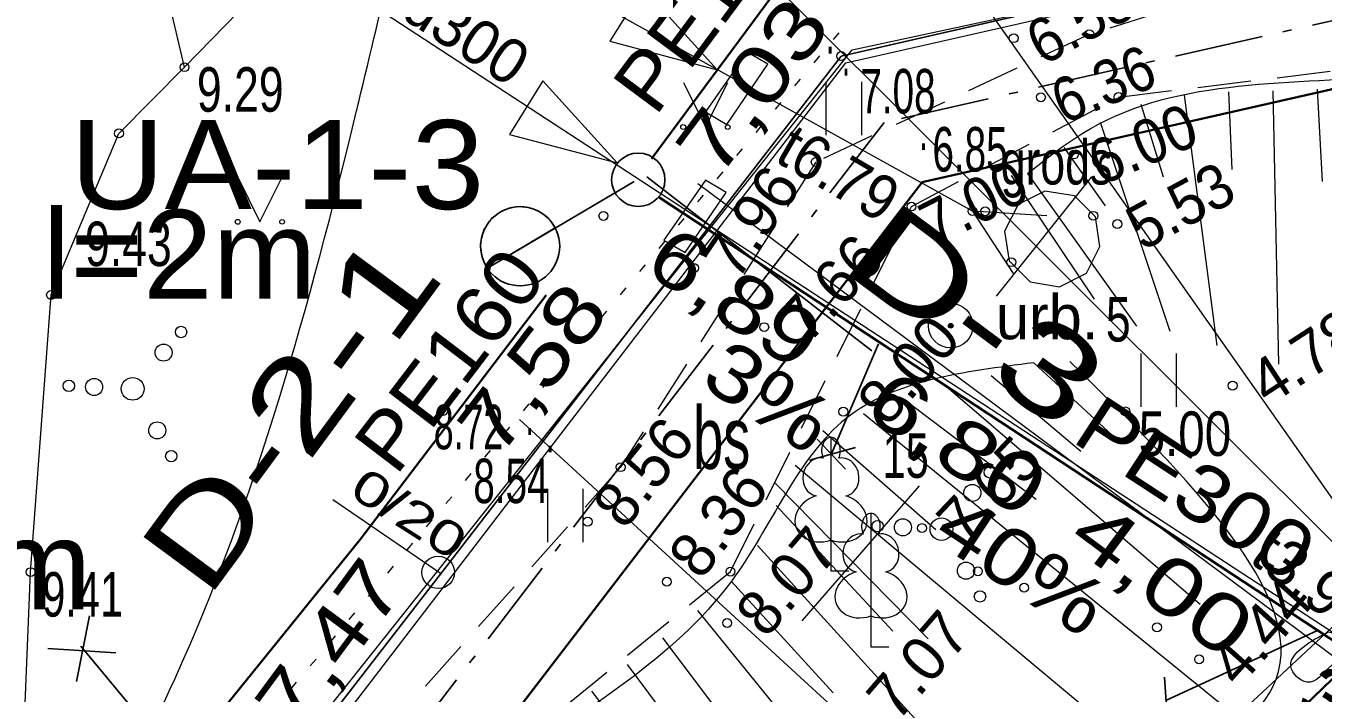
# Model space of a CAD drawing. Extents: x -1320 to -1174, y 762 to 862.
# Drawn here: x -1247.14 to -1232.55, y 822.09 to 829.59 of the extents above; entities that cross this region are included whole.
import ezdxf
from ezdxf.enums import TextEntityAlignment as Align

# ---------------------------------------------------------------- set-up
doc = ezdxf.new("R2010")
doc.units = 0
doc.header["$LTSCALE"] = 0.2
for name, pattern in [('DOT_DASHED', [7.7, 5, -1.2, 0.3, -1.2]), ('DOTTED', [1.5, 0.3, -1.2]), ('MEDIUM_DASHED', [4.5, 3, -1.5])]:
    doc.linetypes.add(name, pattern=pattern)
for name, color, linetype, lineweight in [('1', 7, 'Continuous', 13), ('11', 7, 'Continuous', 35), ('12', 7, 'Continuous', 13), ('19', 7, 'Continuous', 25), ('28', 7, 'Continuous', 13), ('3', 7, 'Continuous', 13), ('30', 7, 'Continuous', 13), ('35', 7, 'Continuous', 25), ('5', 7, 'Continuous', 13), ('55', 7, 'Continuous', 13), ('56', 7, 'Continuous', 13), ('57', 7, 'DOTTED', 13), ('6', 7, 'Continuous', 13), ('61', 7, 'Continuous', 13), ('62', 7, 'Continuous', 13), ('63', 7, 'Continuous', 13)]:
    doc.layers.add(name, color=color, linetype=linetype, lineweight=lineweight)
for name, color, linetype in [('10', 7, 'Continuous'), ('15', 7, 'Continuous'), ('8', 7, 'Continuous')]:
    doc.layers.add(name, color=color, linetype=linetype)

msp = doc.modelspace()

# ---------------------------------------------------------------- hatches: boundary and pattern name
at = {"layer": '6'}
msp.add_hatch(color=256, dxfattribs=at).paths.add_polyline_path([(-1236.709, 826.2181, 1), (-1236.762, 826.2181, 1)])

# ---------------------------------------------------------------- linework, layer by layer
at = {"layer": '1'}
for p, q in [((-1238.894, 830.226), (-1231.002, 822.353)), ((-1228.446, 818.593), (-1236.594, 830.173)), ((-1233.61, 828.848), (-1233.573, 827.973)), ((-1233.11, 828.861), (-1233.048, 825.785)), ((-1232.611, 828.877), (-1232.555, 827.84)), ((-1234.598, 828.708), (-1234.344, 827.894)), ((-1234.109, 828.809), (-1233.743, 825.994)), ((-1235.054, 828.507), (-1234.271, 826.156)), ((-1235.464, 828.221), (-1234.996, 827.565)), ((-1235.871, 827.931), (-1234.647, 826.214)), ((-1239.581, 827.819), (-1230.198, 820.844)), ((-1235.8, 825.801), (-1234.915, 824.985)), ((-1236.28, 825.659), (-1235.273, 824.806)), ((-1236.759, 825.516), (-1233.93, 823.086)), ((-1237.238, 825.374), (-1235.775, 824.269)), ((-1237.718, 825.232), (-1233.202, 821.569)), ((-1241.586, 825.164), (-1230.918, 815.373)), ((-1238.174, 825.038), (-1236.903, 823.928)), ((-1238.484, 824.65), (-1234.223, 821.091)), ((-1242.465, 823.426), (-1243.688, 824.26)), ((-1238.698, 824.198), (-1237.386, 822.782)), ((-1238.91, 823.745), (-1235.858, 820.396)), ((-1239.205, 823.344), (-1238.058, 822.089)), ((-1239.583, 823.017), (-1236.735, 819.506)), ((-1239.977, 822.71), (-1238.971, 821.376)), ((-1240.377, 822.41), (-1237.544, 818.612)), ((-1240.776, 822.109), (-1239.755, 820.789))]:
    msp.add_line(p, q, dxfattribs=at)
msp.add_circle((-1242.502, 823.444), 0.1827, dxfattribs=at)
for points in [[(-1235.871, 827.931), (-1235.167, 828.433), (-1231.672, 829.028), (-1224.12, 831.442)], [(-1235.8, 825.801), (-1237.913, 825.174), (-1239.203, 823.346), (-1241.709, 821.268), (-1246.557, 815.58), (-1256.526, 805.053), (-1260.592, 799.147), (-1261.416, 795.29), (-1262.742, 791.444), (-1262.206, 785.139)]]:
    msp.add_spline(points, degree=3, dxfattribs=at)
at = {"layer": '11'}
for p, q in [((-1240.104, 828.096), (-1238.573, 830.157)), ((-1240.019, 827.663), (-1231.708, 822.202))]:
    msp.add_line(p, q, dxfattribs=at)
msp.add_lwpolyline([(-1245.235, 821.525), (-1243.382, 823.815), (-1241.289, 826.563)], dxfattribs=at)
at = {"layer": '19', "lineweight": 13}
msp.add_spline([(-1253.457, 785.393), (-1253.726, 794.104), (-1251.637, 801.373), (-1250.122, 804.26), (-1247.608, 807.348), (-1239.437, 815.545), (-1236.508, 819.221), (-1228.799, 821.851), (-1223.357, 826.161), (-1220.079, 827.95)], degree=3, dxfattribs=at)
at = {"layer": '28'}
msp.add_lwpolyline([(-1235.654, 827.452), (-1236.491, 827.506), (-1236.033, 826.804)], dxfattribs=at)
at = {"layer": '3'}
for p in [(-1236.491, 827.506), (-1232.369, 822.724)]:
    msp.add_line(p, (-1257.833, 839.343), dxfattribs=at)
at = {"layer": '30'}
msp.add_spline([(-1247.278, 818.829), (-1245.467, 822.244), (-1243.421, 828.633), (-1242.663, 831.887)], degree=3, dxfattribs=at)
at = {"layer": '35'}
msp.add_lwpolyline([(-1264.692, 791.666), (-1263.121, 794.463), (-1262.995, 800.82), (-1256.407, 807.512), (-1249.819, 814.203), (-1245.888, 819.015), (-1242.275, 823.687), (-1240.604, 825.846), (-1237.968, 829.25), (-1236.511, 829.583), (-1228.03, 831.521)], dxfattribs=at)
at = {"layer": '35', "lineweight": 35}
msp.add_lwpolyline([(-1225.362, 830.487), (-1237.056, 827.834), (-1243.981, 818.809), (-1250.833, 810.905), (-1258.147, 803.474), (-1260.339, 800.099), (-1261.472, 796.156), (-1261.529, 794.093), (-1263.29, 790.894)], dxfattribs=at)
at = {"layer": '5'}
for p, q in [((-1238.137, 828.361), (-1238.137, 828.961)), ((-1237.737, 828.361), (-1237.737, 828.961)), ((-1234.594, 825.307), (-1234.594, 825.907)), ((-1234.194, 825.307), (-1234.194, 825.907)), ((-1238.083, 824.961), (-1238.083, 823.808)), ((-1237.993, 824.729), (-1237.994, 824.73)), ((-1241.27, 823.783), (-1241.27, 824.383)), ((-1240.87, 823.783), (-1240.87, 824.383)), ((-1237.633, 824.107), (-1237.633, 822.954)), ((-1238.083, 823.808), (-1238.083, 823.461)), ((-1237.543, 823.875), (-1237.544, 823.876)), ((-1238.083, 823.461), (-1237.883, 823.461)), ((-1237.633, 822.954), (-1237.633, 822.607)), ((-1237.633, 822.607), (-1237.433, 822.607))]:
    msp.add_line(p, q, dxfattribs=at)
for points in [[(-1239.744, 828.953), (-1239.494, 828.453), (-1239.244, 828.953)], [(-1244.758, 827.887), (-1244.508, 827.387), (-1244.258, 827.887)]]:
    msp.add_lwpolyline(points, dxfattribs=at)
for centre, radius in [((-1239.7447, 828.4523), 0.028), ((-1239.2447, 828.4523), 0.0263), ((-1244.7584, 827.3863), 0.028), ((-1244.2584, 827.3863), 0.0263), ((-1245.396, 826.1475), 0.064), ((-1245.5925, 825.9158), 0.096), ((-1245.94, 825.5082), 0.128), ((-1246.6584, 825.5424), 0.064), ((-1246.374, 825.5289), 0.096), ((-1245.6636, 825.0413), 0.096), ((-1245.5061, 824.752), 0.064), ((-1236.296, 824.5695), 0.064), ((-1236.4925, 824.3378), 0.096), ((-1237.274, 823.9509), 0.096), ((-1236.84, 823.9302), 0.128), ((-1237.5584, 823.9644), 0.064), ((-1236.5636, 823.4633), 0.096), ((-1236.4061, 823.174), 0.064)]:
    msp.add_circle(centre, radius, dxfattribs=at)
for centre, major_axis, ratio, start_param, end_param in [((-1238.0826, 824.8112), (0, -0.1499), 0.707107, 3.1453698, 5.2874846), ((-1238.0835, 824.8112), (0, -0.1499), 0.707107, 0.9957007, 3.1378155), ((-1238.2113, 824.5164), (-0.0387, -0.2124), 0.861323, 3.1415927, 6.2831853), ((-1237.9548, 824.5164), (0.0387, -0.2124), 0.861323, 6.2831853, 9.424778), ((-1238.1726, 824.0541), (0.3068, 0.0951), 0.814445, 1.5707963, 4.7520146), ((-1237.9935, 824.0541), (-0.3068, 0.0951), 0.814445, 1.5311707, 4.712389), ((-1237.6326, 823.9572), (0, -0.1499), 0.707107, 3.1453698, 5.2874846), ((-1237.6335, 823.9572), (0, -0.1499), 0.707107, 0.9957007, 3.1378155), ((-1237.7613, 823.6624), (-0.0387, -0.2124), 0.861323, 3.1415927, 6.2831853), ((-1237.5048, 823.6624), (0.0387, -0.2124), 0.861323, 6.2831853, 9.424778), ((-1237.7226, 823.2001), (0.3068, 0.0951), 0.814445, 1.5707963, 4.7520146), ((-1237.5435, 823.2001), (-0.3068, 0.0951), 0.814445, 1.5311707, 4.712389)]:
    msp.add_ellipse(centre, major_axis=major_axis, ratio=ratio, start_param=start_param, end_param=end_param, dxfattribs=at)
at = {"layer": '55'}
msp.add_lwpolyline([(-1279.323, 790.175), (-1264.692, 791.666), (-1263.121, 794.463), (-1263.06, 799.299), (-1247.785, 816.834), (-1237.845, 829.32), (-1225.799, 831.912), (-1223.768, 834.184)], dxfattribs=at)
at = {"layer": '56'}
msp.add_lwpolyline([(-1236.131, 827.282), (-1236.079, 826.949), (-1235.842, 826.711), (-1235.51, 826.657), (-1235.209, 826.809), (-1235.056, 827.108), (-1235.107, 827.441), (-1235.344, 827.679), (-1235.677, 827.733), (-1235.977, 827.581)], close=True, dxfattribs=at)
at = {"layer": '57'}
msp.add_line((-1246.776, 819.001), (-1237.687, 829.874), dxfattribs=at)
at = {"layer": '6'}
for centre, radius in [((-1236.027, 829.4511), 0.05), ((-1235.176, 829.4941), 0.05), ((-1237.968, 829.2502), 0.05), ((-1245.357, 829.1252), 0.05), ((-1235.721, 828.7871), 0.05), ((-1234.848, 828.7902), 0.05), ((-1246.095, 828.3812), 0.05), ((-1235.35, 828.1431), 0.05), ((-1238.254, 828.0592), 0.05), ((-1237.177, 827.5582), 0.05), ((-1236.491, 827.5062), 0.05), ((-1236.348, 827.5052), 0.05), ((-1240.6432, 827.4527), 0.05), ((-1235.131, 827.4542), 0.05), ((-1234.86, 827.3612), 0.05), ((-1236.053, 826.9322), 0.05), ((-1239.625, 826.8672), 0.05), ((-1246.858, 826.5642), 0.05), ((-1236.7352, 826.2183), 0.25), ((-1238.834, 826.2022), 0.05), ((-1236.7355, 826.2181), 0.0265), ((-1233.564, 825.5442), 0.05), ((-1242.4472, 825.2601), 0.05), ((-1237.944, 825.2512), 0.05), ((-1234.77, 825.2542), 0.05), ((-1240.45, 824.6272), 0.05), ((-1240.82, 824.0152), 0.05), ((-1237.059, 823.9422), 0.05), ((-1247.088, 823.4472), 0.05), ((-1239.214, 823.4532), 0.05), ((-1236.43, 823.4572), 0.05), ((-1239.93, 823.3392), 0.05), ((-1235.909, 823.2722), 0.05), ((-1239.251, 822.8752), 0.05), ((-1234.414, 822.8261), 0.05), ((-1233.9405, 822.4659), 0.05)]:
    msp.add_circle(centre, radius, dxfattribs=at)
at = {"layer": '61'}
msp.add_lwpolyline([(-1249.819, 814.203), (-1246.581, 818.124), (-1237.968, 829.25), (-1225.679, 832.058)], dxfattribs=at)
at = {"layer": '62'}
msp.add_spline([(-1254.434, 786.21), (-1255.853, 794.247), (-1253.373, 799.783), (-1252.196, 801.907), (-1252.103, 801.965), (-1250.675, 804.058), (-1247.791, 807.511), (-1245.419, 810.213), (-1244.186, 811.494), (-1242.939, 812.764), (-1240.149, 815.75), (-1236.129, 820.169), (-1233.075, 822.242), (-1235.394, 825.816)], degree=3, dxfattribs=at)
at = {"layer": '63'}
for p, q in [((-1245.357, 829.125), (-1246.012, 831.935)), ((-1235.154, 827.889), (-1236.223, 826.551)), ((-1236.056, 827.906), (-1235.12, 826.518)), ((-1238.713, 824.453), (-1236.99, 822.696)), ((-1237.092, 824.419), (-1238.409, 822.899))]:
    msp.add_line(p, q, dxfattribs=at)
at = {"layer": '63', "lineweight": 25}
for p, q in [((-1240.299, 827.841), (-1241.954, 826.862)), ((-1240.156, 827.892), (-1237.623, 825.936)), ((-1237.548, 826.016), (-1238.081, 824.77)), ((-1238.24, 824.944), (-1237.92, 824.606)), ((-1237.807, 824.849), (-1238.323, 824.707)), ((-1246.425, 822.957), (-1246.573, 822.218)), ((-1232.6, 822.795), (-1234.316, 822.005)), ((-1246.893, 822.588), (-1246.13, 822.539)), ((-1245.613, 821.52), (-1246.524, 822.613)), ((-1234.331, 822.265), (-1234.294, 821.748))]:
    msp.add_line(p, q, dxfattribs=at)
at = {"layer": '63'}
for points in [[(-1256.412, 818.123), (-1256.201, 815.29), (-1252.408, 813.098), (-1251.504, 813.774), (-1247.278, 818.829), (-1247.088, 823.447), (-1246.858, 826.564), (-1246.095, 828.381), (-1245.357, 829.125), (-1242.02, 832.546), (-1243.096, 833.394)], [(-1262.966, 796.388), (-1261.719, 800.729), (-1259.323, 804.418), (-1255.629, 808.17), (-1251.935, 811.923), (-1248.539, 815.84), (-1245.143, 819.757), (-1241.53, 824.466), (-1237.916, 829.176), (-1231.805, 830.562), (-1225.694, 831.949), (-1225.362, 830.487), (-1237.053, 827.834), (-1240.518, 823.322), (-1243.326, 819.676), (-1247.407, 814.857), (-1250.833, 810.905), (-1254.833, 806.84), (-1258.147, 803.474), (-1260.348, 800.104), (-1261.483, 796.15)], [(-1261.483, 796.15), (-1260.348, 800.104), (-1258.147, 803.474), (-1257.342, 804.291), (-1256.78, 804.862), (-1256.04, 805.612), (-1253.626, 808.067), (-1251.48, 810.249), (-1250.651, 811.111), (-1250.414, 811.388), (-1248.806, 813.242), (-1245.075, 817.511), (-1244.093, 818.684), (-1242.558, 820.667), (-1241.555, 821.963), (-1239.557, 824.569), (-1237.053, 827.834), (-1230.901, 829.229)], [(-1231.863, 823.367), (-1235.734, 819.766), (-1239.521, 815.019), (-1242.918, 811.201), (-1245.916, 807.839), (-1248.699, 804.681), (-1251.078, 801.983), (-1252.85, 799.838), (-1253.787, 798.196), (-1254.328, 797.239), (-1254.328, 797.239), (-1255.102, 794.624)]]:
    msp.add_lwpolyline(points, dxfattribs=at)
at = {"layer": '63', "linetype": 'MEDIUM_DASHED'}
for points in [[(-1225.119, 832.074), (-1232.655, 830.279), (-1235.176, 829.494), (-1238.254, 828.059), (-1240.45, 824.627), (-1244.967, 819.561)], [(-1265.079, 785.987), (-1263.807, 789.442), (-1261.536, 795.397), (-1260.86, 799.605), (-1256.627, 805.136), (-1246.564, 815.823), (-1241.769, 821.378), (-1239.214, 823.453), (-1237.177, 827.558), (-1234.848, 828.79), (-1231.517, 829.195), (-1224.557, 831.447)]]:
    msp.add_lwpolyline(points, dxfattribs=at)
at = {"layer": '63', "linetype": 'DOT_DASHED', "lineweight": 25}
for points in [[(-1225.528, 831.218), (-1237.486, 828.505), (-1244.562, 819.283), (-1251.384, 811.414), (-1258.735, 803.946), (-1261.029, 800.414), (-1262.219, 796.272), (-1262.274, 794.295), (-1264.33, 790.56), (-1266.742, 787.222)], [(-1254.918, 786.26), (-1254.605, 794.542), (-1253.865, 797.042), (-1252.437, 799.553), (-1250.698, 801.658), (-1245.95, 807.041), (-1239.139, 814.697), (-1235.363, 819.429), (-1232.239, 822.444), (-1231.619, 822.931), (-1231.44, 822.991), (-1229.31, 823.677), (-1223.125, 826.536)]]:
    msp.add_lwpolyline(points, dxfattribs=at)
at = {"layer": '63'}
for points in [[(-1239.362, 829.097), (-1240.198, 830.019), (-1240.572, 829.417)], [(-1239.027, 829.295), (-1239.495, 828.623), (-1239.255, 828.482), (-1238.793, 829.159)], [(-1240.49, 828.05), (-1241.326, 828.972), (-1241.7, 828.37)], [(-1239.495, 827.853), (-1239.963, 827.181), (-1239.723, 827.04), (-1239.261, 827.717)], [(-1241.954, 826.862), (-1242.004, 826.977), (-1242.027, 827.137), (-1241.989, 827.297), (-1241.891, 827.435), (-1241.798, 827.502), (-1241.704, 827.542), (-1241.595, 827.559), (-1241.484, 827.548), (-1241.384, 827.513), (-1241.322, 827.473), (-1241.266, 827.428), (-1241.208, 827.355), (-1241.186, 827.319)]]:
    msp.add_lwpolyline(points, close=True, dxfattribs=at)
at = {"layer": '63', "lineweight": 35}
msp.add_lwpolyline([(-1254.918, 786.26), (-1254.605, 794.542), (-1253.865, 797.042), (-1252.437, 799.553), (-1251.568, 800.606), (-1250.698, 801.658), (-1248.324, 804.35), (-1245.95, 807.041), (-1242.544, 810.869), (-1239.139, 814.697), (-1237.251, 817.063), (-1235.363, 819.429), (-1233.801, 820.936), (-1232.239, 822.444), (-1231.619, 822.931), (-1229.31, 823.677), (-1223.125, 826.536)], dxfattribs=at)
at = {"layer": '63', "lineweight": 25}
for centre, radius in [((-1240.251, 827.859), 0.3), ((-1241.58, 827.112), 0.445)]:
    msp.add_circle(centre, radius, dxfattribs=at)
at = {"layer": '63'}
msp.add_spline([(-1232.488, 822.774), (-1232.737, 822.63), (-1232.908, 822.387), (-1232.73, 822.211), (-1232.449, 822.401), (-1232.311, 822.574), (-1232.366, 822.733), (-1232.488, 822.774)], degree=3, dxfattribs=at)

# ---------------------------------------------------------------- texts
at = {"layer": '1', "width": 1.4}
msp.add_text('0/20', height=0.384, rotation=327.602, dxfattribs=at).set_placement((-1242.9319, 823.9429), align=Align.CENTER)
at = {"layer": '10', "width": 0.65}
msp.add_text('bs', height=0.7, dxfattribs=at).set_placement((-1239.3125, 824.607), align=Align.CENTER)
at = {"layer": '11'}
for s, rotation, p in [('d300', 327.224, (-1242.3198, 829.2935)), ('t3.99', 323.042, (-1232.7998, 823.1272))]:
    msp.add_text(s, height=0.5, rotation=rotation, dxfattribs=at).set_placement(p, align=Align.CENTER)
at = {"layer": '11', "width": 0.95}
msp.add_text('t6.79', height=0.5, rotation=329.713, dxfattribs=at).set_placement((-1238.1236, 827.7199), align=Align.CENTER)
at = {"layer": '12', "width": 0.7}
msp.add_text(' 15', height=0.5, dxfattribs=at).set_placement((-1237.633, 824.507))
at = {"layer": '15', "width": 0.75}
msp.add_text('grods', height=0.5, dxfattribs=at).set_placement((-1236.173, 827.806))
at = {"layer": '6'}
msp.add_text('urb.', height=0.5, dxfattribs=at).set_placement((-1236.227, 826.066))
at = {"layer": '6', "width": 0.75}
msp.add_text('5', height=0.5, dxfattribs=at).set_placement((-1234.8505, 826.04), align=Align.CENTER)
at = {"layer": '63'}
for s, height, rotation, width, p in [('PE160', 0.64, 53.388, 1.1, (-1239.217, 829.6932)), ('7,03', 0.64, 53.388, 1.3, (-1238.7092, 828.7222)), ('D-3', 1, 323.374, 1.45, (-1236.7393, 825.932)), ('6,89', 0.64, 326.695, 1.25, (-1239.3392, 826.2677)), ('D-2-1', 1, 53.597, 1.35, (-1243.7612, 824.9468)), ('PE160', 0.64, 52.705, 1.1, (-1242.1212, 825.6406)), ('7,58', 0.64, 52.705, 1.25, (-1241.1869, 825.5491)), ('3%', 0.64, 326.693, 1.2, (-1238.9552, 825.1563)), ('6,80', 0.64, 326.695, 1.3, (-1236.8397, 824.6305)), ('PE300', 0.64, 326.87, 1.15, (-1234.1539, 824.119)), ('40%', 0.64, 326.693, 1.2, (-1236.1022, 823.2552)), ('4,00', 0.64, 323.374, 1.35, (-1234.5409, 823.1123)), ('7,47', 0.64, 53.597, 1.25, (-1243.4691, 822.4416)), ('3,90', 0.64, 326.87, 1.25, (-1232.0249, 821.3525))]:
    msp.add_text(s, height=height, rotation=rotation, dxfattribs=dict(at, width=width)).set_placement(p, align=Align.CENTER)
for s, width, p in [('UA-1-3', 1.1, (-1244.313, 827.53)), ('PE600, l=2m', 1.05, (-1247.911, 826.521)), ('PE600, l=2m', 1.05, (-1250.442, 823.028))]:
    msp.add_text(s, height=1, dxfattribs=dict(at, width=width)).set_placement(p, align=Align.CENTER)
at = {"layer": '8'}
for s, rotation, width, p in [(' 6.58', 28.573, 0.95, (-1235.857, 829.05)), (' 6.36', 22.605, 0.9, (-1235.618, 828.415)), (' 6.00', 23.171, 0.95, (-1235.207, 827.719)), (' 7.00', 26.785, 0.95, (-1237.074, 827.02)), (' 5.53', 28.383, 0.95, (-1234.733, 826.97))]:
    msp.add_text(s, height=0.5, rotation=rotation, dxfattribs=dict(at, width=width)).set_placement(p)
for s, width, p in [('.', 0.5, (-1238.139, 829.279)), (' 9.29', 0.75, (-1245.357, 828.625)), ('.', 0.5, (-1237.961, 829.03)), ('7.08', 0.65, (-1237.752, 828.605)), ('6.85', 0.65, (-1236.941, 827.952)), ('.', 0.5, (-1237.089, 828.193)), (' 9.43', 0.75, (-1246.616, 826.889)), ('8.72', 0.6, (-1242.552, 824.829)), (' 5.00', 0.8, (-1234.77, 824.754)), ('.', 0.5, (-1241.52, 824.989)), ('.', 0.5, (-1241.289, 824.793)), ('8.54', 0.65, (-1242.107, 824.223)), (' 9.41', 0.7, (-1247.088, 822.947))]:
    msp.add_text(s, height=0.5, dxfattribs=dict(at, width=width)).set_placement(p)
for s, rotation, p in [(' 7.96', 55.761, (-1239.243, 826.555)), (' 7.66', 47.113, (-1238.468, 825.862)), (' 4.78', 32.959, (-1233.319, 825.206)), (' 8.00', 49.596, (-1237.563, 824.927)), (' 8.56', 51.117, (-1240.524, 823.764)), (' 7.65', 46.428, (-1236.697, 823.598)), (' 8.36', 53.061, (-1239.655, 823.195)), (' 8.07', 49.339, (-1238.934, 822.549)), (' 4.44', 48.23, (-1233.618, 821.995)), (' 7.07', 49.117, (-1237.461, 821.606))]:
    msp.add_text(s, height=0.5, rotation=rotation, dxfattribs=at).set_placement(p)

doc.saveas('drawing.dxf')
